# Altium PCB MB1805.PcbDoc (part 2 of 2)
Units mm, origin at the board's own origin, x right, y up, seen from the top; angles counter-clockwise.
Board outline 43 x 47.02 mm, 4 copper layers (Top Layer, Internal 1, Internal 2, Bottom Layer), stack 1.565 mm thick; 110 components, 91 nets, 377 pads, 610 vias.
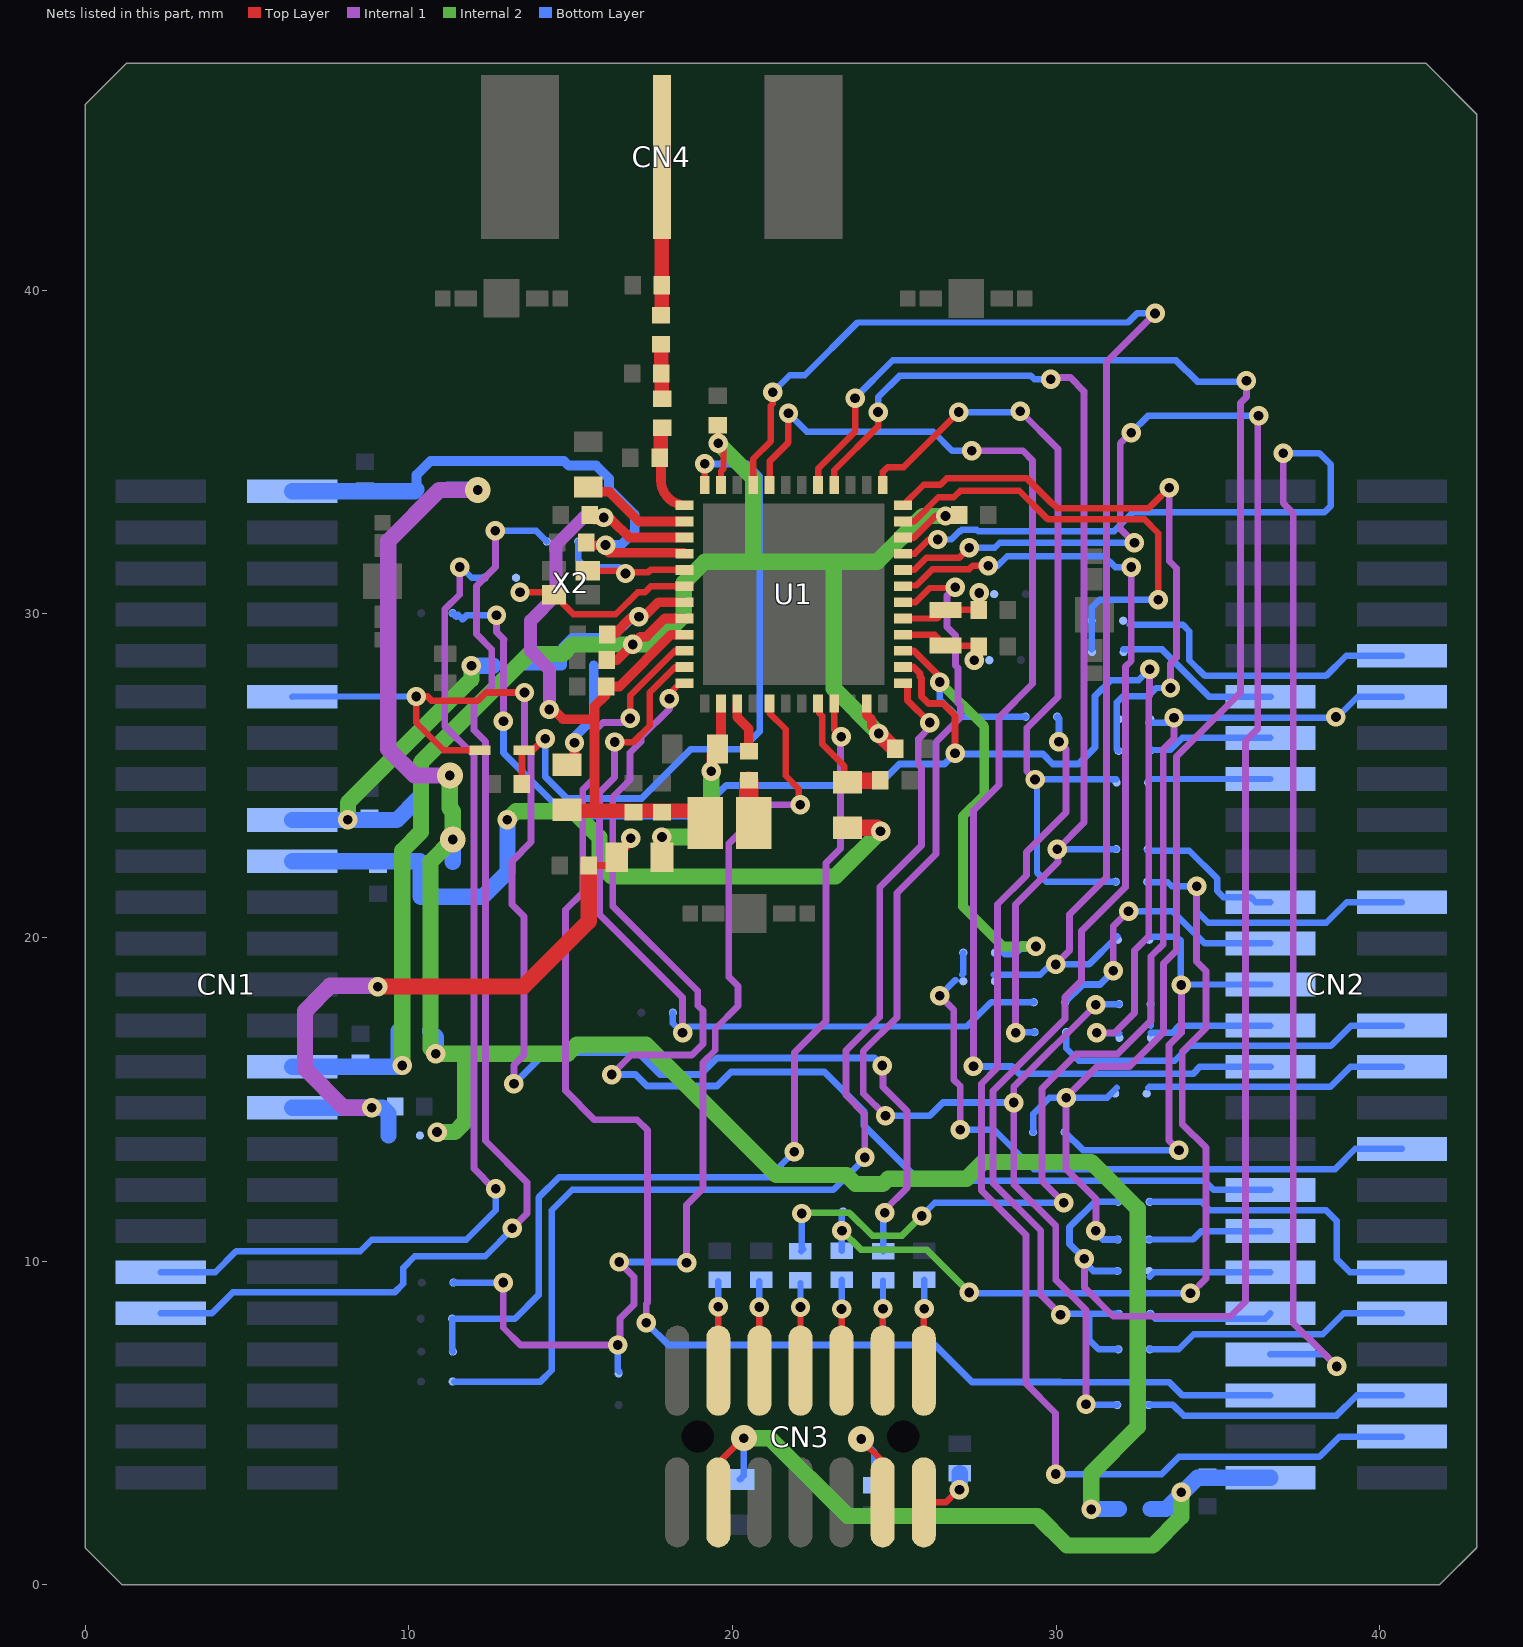
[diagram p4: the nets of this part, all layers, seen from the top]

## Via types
v1: diameter 0.6, hole 0.3, Top Layer to Bottom Layer, tented both sides, 605 vias
v2: diameter 0.8, hole 0.3, Top Layer to Bottom Layer, tented both sides, 5 vias

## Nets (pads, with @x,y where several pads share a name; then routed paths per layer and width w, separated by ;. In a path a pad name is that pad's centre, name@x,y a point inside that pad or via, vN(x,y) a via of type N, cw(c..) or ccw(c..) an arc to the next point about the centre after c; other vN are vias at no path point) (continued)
GPIO30: CN2.10 SB13.2 | length 9.8
  Bottom Layer w0.2: 32.276,29.662 33.918,29.662 34.118,29.463 34.118,28.569 34.604,28.083 38.338,28.083 38.963,28.708 CN2.10@40.688,28.708
GPIO31: CN2.11 SB10.2 | length 5.2
  Bottom Layer w0.21: SB10.2@32.077,28.905 33.271,28.905 34.737,27.438 CN2.11@36.624,27.438
GPIO32: CN2.12 R4.2 SB11.2 | length 35.9
  Internal 1 w0.21: v1(30.239,11.802) 29.562,12.479 29.562,15.337 30.624,16.399 31.901,16.399 32.931,17.429 32.931,19.422 33.312,19.803 33.312,25.822 33.643,26.153 v1(33.643,26.788)
  Internal 2 w0.21: v1(22.136,11.471) 22.195,11.471 22.216,11.493 23.611,11.493 24.318,10.786 25.235,10.786 v1(25.845,11.395)
  Bottom Layer w0.2: R4.2@22.118,10.302 22.187,10.372 22.136,10.423 v1(22.136,11.471) ; v1(25.845,11.395) 26.251,11.802 v1(30.239,11.802) ; SB11.2@32.853,26.641 33.496,26.641 v1(33.643,26.788) 38.672,26.788 39.323,27.438 CN2.12@40.688,27.438
  other v1: 38.646,26.813
GPIO33: CN2.13 SB7.2 | length 3.9
  Bottom Layer w0.2: SB7.2@32.903,25.843 SB7.2@32.935,25.812 ; SB7.2@32.938,25.794 33.523,25.794 33.897,26.168 CN2.13@36.624,26.168
GPIO34: CN2.15 SB33.1 | length 3.8
  Bottom Layer w0.2: SB33.1@32.844,24.832 32.91,24.898 CN2.15@36.624,24.898
GPIO37: CN2.21 SB26.1 | length 4.7
  Bottom Layer w0.2: SB26.1@32.824,22.679 34.119,22.679 34.977,21.821 34.977,21.44 35.167,21.25 36.005,21.25 36.167,21.088 CN2.21@36.624,21.088
GPIO38: CN2.22 R5.2 SB8.1 SB35.1 | length 35.3
  Internal 1 w0.21: v1(34.151,9.008) 34.176,9.008 34.633,9.465 34.633,13.505 33.897,14.242 33.897,16.47 34.633,17.207 34.633,18.964 34.343,19.255 v1(34.343,21.581)
  Internal 2 w0.21: v1(23.381,10.938) 23.965,10.354 25.997,10.354 v1(27.318,9.033)
  Bottom Layer w0.2: R5.2@23.376,10.328 23.376,11.402 ; v1(27.318,9.033) v1@27.343,9.008 ; SB35.1@32.829,21.708 33.448,21.708 33.575,21.581 v1(34.343,21.581) 34.343,20.813 34.701,20.454 38.351,20.454 38.985,21.088 CN2.22@40.688,21.088
  Bottom Layer w0.21: v1@27.343,9.008 v1(34.151,9.008)
GPIO39: CN2.23 SB28.1 | length 8.7
  Internal 1 w0.21: v1(31.763,18.972) 31.763,20.336 v1(32.239,20.813)
  Bottom Layer w0.2: v1(32.239,20.813) 33.597,20.813 34.592,19.818 CN2.23@36.624,19.818
  Bottom Layer w0.21: SB28.1@30.282,18 30.831,18.548 31.355,18.548 31.763,18.956 v1(31.763,18.972)
GPIO41: CN2.25 SB22.1 SB31.2 | length 14.3
  Internal 1 w0.21: v1(33.795,13.427) 33.49,13.732 33.49,16.678 33.871,17.059 v1(33.871,18.533)
  Bottom Layer w0.2: SB31.2@32.899,20.027 33.732,20.027 33.859,19.901 v1@33.859,18.533 ; v1@33.871,18.548 CN2.25@36.624,18.548
  Bottom Layer w0.21: SB22.1@30.266,13.988 30.827,13.427 v1(33.795,13.427)
GPIO42: CN2.27 SB23.2 SB36.2 | length 4.5
  Bottom Layer w0.2: 32.921,17.278 SB36.2@32.921,17.941 ; 32.93,17.044 32.921,17.053 33.585,17.053 33.811,17.278 CN2.27@36.624,17.278
GPIO43: CN2.28 SB27.1 | length 11.5
  Bottom Layer w0.2: SB27.1@30.31,17.075 30.31,16.582 30.696,16.196 33.668,16.196 34.125,16.653 38.494,16.653 39.119,17.278 CN2.28@40.688,17.278
GPIO44: CN2.29 U1.32 | length 39.4
  Top Layer w0.2: U1.32@21.145,33.983 21.145,34.711 21.73,35.297 v1(21.73,36.198)
  Internal 1 w0.21: v1(27.394,35.043) 28.207,35.043 28.969,35.043 29.274,34.738 29.274,27.842 28.237,26.805 28.237,24.709 27.445,23.917 v1(27.445,16.018)
  Bottom Layer w0.2: v1(21.73,36.198) 22.302,35.627 26.2,35.627 26.784,35.043 v1(27.394,35.043)
  Bottom Layer w0.21: v1(27.445,16.018) 28.639,16.018 28.867,15.789 34.227,15.789 34.446,16.008 CN2.29@36.624,16.008
GPIO45: CN2.30 SB24.1 | length 8.1
  Bottom Layer w0.2: 32.851,15.354 32.88,15.383 33.708,15.383 33.713,15.388 34.252,15.388 34.257,15.383 38.469,15.383 39.094,16.008 CN2.30@40.688,16.008
GPIO46: CN2.34 SB20.2 SB32.2 | length 20.3
  Internal 1 w0.21: v1(26.404,18.202) 26.835,17.771 26.835,15.612 27.039,15.408 v1(27.039,14.062)
  Bottom Layer w0.2: v1(26.404,18.202) 26.886,18.685 26.894,18.685 ; v1@27.039,14.163 v1(27.039,14.062) 28.086,14.062 29.305,12.843 38.621,12.843 39.246,13.468 CN2.34@40.688,13.468 ; 27.094,18.845 27.13,18.88 SB20.2@27.13,19.531
GPIO47: CN2.35 U1.48 | length 39.2
  Top Layer w0.2: v1(18.052,27.377) 17.906,27.377 17.898,27.385 18.371,27.858 U1.48@18.52,27.858
  Internal 1 w0.21: v1(16.269,15.764) 16.872,16.367 18.744,16.367 19.085,16.708 19.085,17.742 18.926,17.9 18.926,18.345 16.299,20.972 16.299,22.556 16.299,24.334 16.835,24.87 16.835,25.709 17.177,26.051 17.177,26.193 18.052,27.068 v1(18.052,27.377)
  Bottom Layer w0.2: 27.586,12.487 34.582,12.487 34.871,12.198 CN2.35@36.624,12.198
  Bottom Layer w0.21: v1(16.269,15.764) 16.999,15.764 17.355,15.408 19.519,15.408 19.953,15.842 22.845,15.842 24.061,14.626 24.061,14.184 25.758,12.487 27.586,12.487
GPIO49: CN2.37 SB29.1 | length 3.9
  Bottom Layer w0.2: SB29.1@32.877,10.668 34.23,10.668 34.49,10.928 CN2.37@36.624,10.928
GPIO50: CN2.39 SB12.2 | length 3.8
  Bottom Layer w0.2: 32.897,9.521 33.034,9.658 CN2.39@36.624,9.658
GPIO51: CN2.40 SB15.2 | length 9.4
  Bottom Layer w0.2: SB15.2@32.889,11.832 34.481,11.832 34.741,11.573 38.342,11.573 38.672,11.243 38.672,10.066 39.08,9.658 CN2.40@40.688,9.658
GPIO52: CN2.41 SB16.2 | length 3.8
  Bottom Layer w0.2: SB16.2@32.91,8.371 33.061,8.22 36.456,8.22 CN2.41@36.624,8.388
GPIO53: CN2.42 SB18.2 | length 8.3
  Bottom Layer w0.2: SB18.2@32.898,7.274 33.789,7.274 34.252,7.738 38.24,7.738 38.891,8.388 CN2.42@40.688,8.388
GPIO54: CN2.43 U1.21 | length 47.9
  Top Layer w0.2: U1.21@25.27,31.858 25.625,31.858 26.067,32.299 v1(26.342,32.299)
  Internal 1 w0.21: v1(37.021,34.966) 37.021,33.417 37.326,33.112 37.326,8.093 38.195,7.224 v1(38.672,6.747)
  Bottom Layer w0.2: v1(26.342,32.299) 26.759,32.299 27.013,32.553 27.048,32.553 27.09,32.595 27.546,32.595 27.588,32.553 31.79,32.553 32.375,33.138 38.291,33.138 38.494,33.341 38.494,34.611 38.138,34.966 v1(37.021,34.966) ; CN2.43@36.624,7.118 38.3,7.118 v1(38.672,6.747)
GPIO55: CN2.45 U1.46 | length 44.9
  Top Layer w0.2: v1(16.835,26.769) 16.835,26.934 16.835,27.471 18.222,28.858 U1.46@18.52,28.858
  Internal 1 w0.21: v1(16.835,26.769) 16.706,26.64 15.995,26.64 15.736,26.38 15.736,24.933 15.374,24.571 15.374,21.397 14.836,20.858 14.836,15.267 15.736,14.367 17.056,14.367 17.374,14.05 17.374,8.718 17.336,8.68 v1(17.336,8.093)
  Bottom Layer w0.2: 30.137,6.264 33.49,6.264 33.906,5.848 CN2.45@36.624,5.848
  Bottom Layer w0.21: v1(17.336,8.093) 18.016,7.413 26.253,7.413 27.402,6.264 30.137,6.264
GPIO56: CN2.46 SB34.2 | length 8.2
  Bottom Layer w0.2: SB34.2@32.865,5.556 33.611,5.556 33.941,5.226 38.667,5.226 39.289,5.848 CN2.46@40.688,5.848
GPIO57: CN2.48 SB42.2 | length 36.7
  Internal 1 w0.21: v1(29.985,3.42) 29.985,5.299 29.071,6.214 29.071,10.811 27.694,12.188 27.694,15.482 28.191,15.979 28.191,21.029 29.085,21.922 29.085,22.636 30.31,23.861 30.31,25.828 v1(30.087,26.051)
  Bottom Layer w0.2: v1(29.985,3.42) 33.262,3.42 33.795,3.953 38.138,3.953 38.764,4.578 CN2.48@40.688,4.578
  Bottom Layer w0.21: SB42.2@30.033,26.823 30.087,26.769 v1(30.087,26.051)
NetC6_1: C6.1 L4.1 U1.2 | length 5.3
  Top Layer w0.3: v1(19.347,25.142) 19.347,25.638 C6.1@19.537,25.829 ; C6.1@19.645,26.051 U1.2@19.645,27.233
  Internal 2 w0.512: v1(17.82,23.107) 19.032,23.107 19.347,23.421 v1(19.347,25.142)
NetC7_2: C7.2 D1.1 U1.36 | length 21.5
  Top Layer w0.21: C7.2@13.492,24.745 13.492,25.722 D1.1@13.554,25.784 13.827,25.784 v1@14.212,26.169 ; v1(14.212,26.145) v1@14.212,26.169 ; v1@14.297,26.254 v1@14.212,26.169 ; v1@14.332,26.289 v1@14.212,26.169 ; U1.36@19.145,33.983 v1(19.145,34.636)
  Bottom Layer w0.21: v1(14.212,26.145) 14.212,24.969 14.886,24.295 17.193,24.295 18.717,25.82 20.293,25.82 20.841,26.368 20.841,27.651 20.841,34.255 20.46,34.636 v1(19.145,34.636)
NetC8_2: C8.2 SB38.1 U1.16 X1.2 | length 2.3
  Top Layer w0.2: U1.16@25.27,29.358 26.246,29.358 X1.2@26.581,29.022 27.406,29.022 C8.2@27.445,29.062
  other v1: 27.47,28.566
NetC9_2: C9.2 SB37.1 U1.17 X1.1 | length 2.3
  Top Layer w0.2: U1.17@25.27,29.858 26.317,29.858 X1.1@26.581,30.122 27.449,30.122 C9.2@27.453,30.119
  other v1: 27.623,30.648
NetC11_2: C11.2 U1.38 | length 3.4
  Top Layer w0.3: C11.2@15.545,33.92 15.693,33.772 16.198,33.772 17.112,32.858 U1.38@18.52,32.858
NetC12_2: C12.2 L1.1 U1.37 | length 2.8
  Top Layer w0.2: L1.1@17.785,35.7 L1.1@17.831,35.745
  Top Layer w0.3: L1.1@17.785,35.7 L1.1@17.789,35.696 ; C12.2@17.789,34.865 C12.2@17.747,34.823 17.789,34.782 17.789,34.131 ccw(c18.563,34.131) U1.37@18.52,33.358
  Top Layer w0.45: C12.2@17.789,34.865 L1.1@17.789,35.696
NetC13_2: C13.2 L1.2 L2.1 | length 1.7
  Top Layer w0.45: L2.1@17.796,38.326 17.801,38.321 17.801,37.47 C13.2@17.804,37.467 ; C13.2@17.805,37.432 17.818,37.419 17.818,36.658 L1.2@17.831,36.645
NetC14_2: C14.2 CN4.1 L2.2 | length 4.9
  Top Layer w0.45: L2.2@17.796,39.226 L2.2@17.808,39.237 ; L2.2@17.811,39.231 C14.2@17.811,40.152 ; C14.2@17.816,40.157 CN4.1@17.816,44.118
  Top Layer w0.5: L2.2@17.808,39.231 L2.2@17.811,39.231 ; C14.2@17.811,40.152 C14.2@17.816,40.157 ; CN4.1@17.816,44.118 CN4.1@17.819,44.12
NetC15_1: C15.1 SB6.2 SB41.1 U1.43 | length 7.3
  Top Layer w0.3: C15.1@16.123,29.369 16.35,29.369 16.839,29.858 17.205,29.858 17.705,30.358 U1.43@18.52,30.358
  Bottom Layer w0.2: SB41.1@14.725,28.401 SB41.1@14.736,28.411
  Bottom Layer w0.3: SB6.2@13.571,28.401 SB41.1@14.725,28.401 ; SB41.1@14.736,28.411 14.736,28.942 15.048,29.254 16.247,29.254 16.905,29.912 v1(17.108,29.912)
NetC20_2: C20.2 L3.2 U1.8 | length 4.1
  Top Layer w0.2: U1.8@22.645,27.233 22.683,27.195 22.683,26.936 22.77,26.848 22.77,25.979 23.45,25.299 L3.2@23.45,24.977 ; L3.2@23.335,24.977 L3.2@23.45,24.977 ; L3.2@23.45,24.694 L3.2@23.45,24.977 ; L3.2@23.668,25.013 23.632,24.977 L3.2@23.45,24.977
  Top Layer w0.5: L3.2@23.549,24.794 23.6,24.845 C20.2@24.435,24.845
NetC23_2: C23.2 C24.1 C25.1 C26.1 L6.2 L7.2 U1.39 U1.45 | length 23.9
  Top Layer w0.3: v1(14.34,27.046) 14.466,27.046 14.616,26.896 14.765,26.747 15.735,26.747 ; C26.1@15.588,33.057 15.735,32.909 v1@16.268,32.909 ; 15.735,23.911 15.735,26.747 ; v1@16.024,32.909 v1@16.268,32.909 ; U1.45@18.52,29.358 18.107,29.358 16.508,27.759 C24.1@16.102,27.759 16.102,27.514 15.735,27.148 15.735,26.747 ; U1.39@18.52,32.358 16.818,32.358 v1@16.268,32.909
  Top Layer w0.45: L7.2@14.886,23.943 14.918,23.911 15.735,23.911 16.941,23.911 17.291,23.911 17.825,23.911 18.114,23.911 18.732,23.911 L6.2@19.098,23.545
  Internal 1 w0.4: v1(14.34,27.046) 14.34,28.283 13.765,28.859 13.765,29.791 14.546,30.572 14.546,32.126 15.399,32.98 v1(16.024,32.98)
NetCN3_4: CN3.4 R2.1 | length 2.8
  Top Layer w0.2: CN3.4@19.561,6.614 v1(19.561,8.589) v1@19.561,8.639
  Bottom Layer w0.2: v1(19.561,8.589) R2.1@19.561,9.384
NetCN3_6: CN3.6 R3.1 | length 2.8
  Top Layer w0.2: CN3.6@20.831,6.614 v1(20.831,8.579)
  Bottom Layer w0.2: v1(20.831,8.579) R3.1@20.831,9.372
NetCN3_8: CN3.8 R4.1 | length 2.7
  Top Layer w0.2: CN3.8@22.101,6.614 v1(22.101,8.579)
  Bottom Layer w0.2: v1(22.101,8.579) R4.1@22.101,9.31
NetCN3_10: CN3.10 R5.1 | length 2.8
  Top Layer w0.2: CN3.10@23.371,6.614 v1(23.371,8.519)
  Bottom Layer w0.2: v1(23.371,8.519) R5.1@23.371,9.423
NetCN3_11: CN3.11 R6.2 | length 3.9
  Top Layer w0.2: v2(23.976,4.504) 23.951,4.504 24.641,3.814 CN3.11@24.641,2.544
  Bottom Layer w0.2: v2(23.976,4.504) 24.386,4.094 R6.2@24.386,3.081
NetCN3_12: CN3.12 R7.1 | length 2.8
  Top Layer w0.2: CN3.12@24.641,6.614 24.641,8.519 v1(24.651,8.529)
  Bottom Layer w0.2: v1(24.651,8.529) R7.1@24.651,9.396
NetCN3_13: CN3.13 R9.2 | length 1.6
  Top Layer w0.2: CN3.13@25.911,2.544 26.591,2.544 v1@26.901,2.854
  Bottom Layer w0.5: v1@27.024,2.947 R9.2@27.024,3.45
  other v1: 27.013,2.937
NetCN3_14: CN3.14 R8.1 | length 2.8
  Top Layer w0.2: CN3.14@25.911,6.614 25.911,8.539 25.921,8.529 v1(25.926,8.529)
  Bottom Layer w0.2: v1(25.926,8.529) R8.1@25.926,9.424
NetL5_1: L5.1 U1.3 | length 1.6
  Top Layer w0.3: U1.3@20.145,27.233 20.145,26.809 20.505,26.448 L5.1@20.505,25.788
NetL5_2: L5.2 L6.1 | length 1.3
  Top Layer w0.6: L5.2@20.505,24.838 20.505,23.638 L6.1@20.598,23.545
NetL7_1: L7.1 SB41.2 | length 3.3
  Top Layer w0.3: L7.1@15.006,25.483 15.058,25.483 15.118,25.543 v1(15.118,26.02)
  Bottom Layer w0.3: v1(15.118,26.02) 15.118,26.191 15.711,26.784 SB41.2@15.711,28.411
NetSB1_1: SB1.1 SB2.1 SB3.1 SB4.1 SB5.1 SB43.1 | length 62.5
  Internal 1 w0.5: v2(11.265,25.01) 10.173,25.01 9.36,25.822 9.36,32.249 10.941,33.829 v2(12.129,33.829)
  Internal 2 w0.5: v1(10.871,13.988) 11.42,13.988 11.732,14.3 11.732,16.388 11.71,16.41 ; v2(11.265,25.01) 11.265,23.994 11.355,23.904 v2(11.355,23.028) 10.671,22.344 10.671,16.573 v1(10.833,16.41) 11.71,16.41 ; v1(31.087,2.327) 31.087,3.439 32.525,4.877 32.525,11.624 31.086,13.063 27.744,13.063 27.229,12.548 24.813,12.548 24.645,12.38 23.804,12.38 23.519,12.665 21.351,12.665 17.327,16.688 15.187,16.688 14.909,16.41 11.71,16.41
  Bottom Layer w0.5: SB4.1@10.651,17.107 10.84,16.918 10.84,16.41 v1(10.833,16.41) ; SB2.1@11.214,33.846 12.101,33.846 12.123,33.823 v2(12.129,33.829) ; v2(11.265,25.01) 11.269,25.006 SB3.1@11.269,24.295 ; SB1.1@11.355,22.342 v2(11.355,23.028) ; v1(31.087,2.327) 31.103,2.343 SB5.1@31.947,2.343
NetSB7_1: SB7.1 SB11.1 U1.24 | length 18.9
  Top Layer w0.2: U1.24@25.27,33.358 25.906,33.994 26.425,33.994 26.617,34.187 29.098,34.187 29.859,33.426 29.876,33.426 30.032,33.27 32.866,33.27 33.022,33.426 v1(33.496,33.9)
  Internal 1 w0.21: v1(33.496,33.9) 33.496,31.633 33.719,31.41 33.719,28.646 33.535,28.462 v1(33.535,27.71)
  Bottom Layer w0.2: SB7.1@31.928,25.767 31.878,25.817 31.878,27.264 32.077,27.462 32.842,27.462 33.089,27.71 v1(33.535,27.71)
NetSB8_2: SB8.2 SB9.2 U1.13 | length 35
  Top Layer w0.21: U1.13@25.27,27.858 25.359,27.858 25.412,27.805 25.412,27.327 v1(26.096,26.643)
  Internal 1 w0.21: v1(24.085,13.205) 24.085,14.552 23.508,15.129 23.508,16.504 24.549,17.546 24.549,21.544 25.845,22.84 25.845,25.238 25.743,25.34 25.743,26.138 26.096,26.491 v1(26.096,26.643)
  Bottom Layer w0.2: SB9.2@11.4,6.277 11.897,6.277 12.462,6.277 14.067,6.277 14.415,6.625 14.415,11.573 15.05,12.208 23.12,12.208 SB8.2@23.421,12.509 24.118,13.205 v1(24.085,13.205)
NetSB10_1: SB10.1 SB13.1 U1.23 | length 14.3
  Top Layer w0.2: U1.23@25.27,32.858 25.613,32.858 26.359,33.604 26.841,33.604 27.043,33.805 28.865,33.805 29.751,32.92 32.736,32.92 33.16,32.496 v1(33.16,30.437)
  Bottom Layer w0.2: SB10.1@31.102,28.905 31.102,29.7 31.105,29.704 31.105,30.2 31.343,30.437 v1(33.16,30.437)
NetSB12_1: SB12.1 SB15.1 U1.20 | length 53.8
  Top Layer w0.2: U1.20@25.27,31.358 25.621,31.358 26.003,31.741 27.013,31.741 v1(27.318,32.045)
  Internal 1 w0.21: v1(30.874,10.074) 30.874,9.185 31.763,8.296 35.395,8.296 35.852,8.754 35.852,26.076 36.233,26.457 36.233,36.075 36.279,36.121 36.267,36.133 v1(36.256,36.121) ; v1(32.322,35.601) 31.98,35.26 31.98,32.637 v1(32.42,32.198)
  Bottom Layer w0.2: v1(27.318,32.045) 28.105,32.045 28.258,32.198 32.351,32.198 32.434,32.116 32.468,32.15 v1(32.42,32.198)
  Bottom Layer w0.21: SB12.1@31.897,9.698 31.149,9.698 30.874,9.973 v1(30.874,10.074) 30.417,10.532 30.417,11.055 31.194,11.832 SB15.1@31.914,11.832 ; v1(32.322,35.601) 32.842,36.121 v1(36.256,36.121)
NetSB14_2: SB14.2 SB17.2 U1.9 | length 30
  Top Layer w0.2: U1.9@23.145,27.233 23.145,26.418 v1(23.362,26.201)
  Internal 1 w0.21: v1(21.912,13.376) 21.912,16.446 22.888,17.422 22.888,22.299 23.335,22.747 23.335,26.174 v1(23.362,26.201)
  Bottom Layer w0.2: SB14.2@11.359,7.205 11.339,7.224 SB17.2@11.339,8.221 13.278,8.221 14.008,8.952 14.008,11.964 14.643,12.598 21.134,12.598 v1(21.912,13.376)
NetSB16_1: SB16.1 SB18.1 U1.19 | length 36.7
  Top Layer w0.2: U1.19@25.27,30.858 25.29,30.878 25.678,30.878 26.185,31.385 27.318,31.385 27.42,31.487 v1(27.902,31.487)
  Internal 1 w0.21: v1(30.137,8.347) 29.528,8.957 29.528,10.938 28.054,12.412 28.054,15.256 30.277,17.48 30.277,18.156 30.788,18.666 30.788,20.199 32.144,21.555 32.144,28.372 32.322,28.55 v1(32.322,31.447)
  Internal 2 w0.21: v1@30.087,8.398 v1(30.137,8.347)
  Bottom Layer w0.2: v1(27.902,31.487) 28.191,31.487 28.487,31.783 28.943,31.783 31.489,31.783 31.825,31.447 v1(32.322,31.447) ; v1@30.417,8.371 31.026,8.371 ; SB18.1@31.923,7.274 31.312,7.274 31.026,7.56 31.026,8.371 ; SB16.1@31.935,8.371 31.026,8.371
NetSB19_2: SB19.2 SB21.2 U1.5 | length 32.6
  Top Layer w0.2: U1.5@21.145,27.233 21.145,26.932 21.645,26.432 21.645,24.996 22.043,24.597 v1@22.043,24.136
  Internal 1 w0.21: v1(12.916,9.338) 12.916,7.941 13.45,7.407 v1(16.452,7.407) 16.523,7.407 16.523,8.225 16.959,8.661 16.959,9.511 v1(16.498,9.973) ; v1(18.58,9.947) 18.58,11.736 19.085,12.24 19.085,16.133 19.468,16.516 19.468,17.181 20.168,17.881 20.168,18.502 19.886,18.784 19.886,22.907 21.083,24.104 v1(22.096,24.104)
  Bottom Layer w0.2: SB19.2@11.375,9.337 11.402,9.363 11.427,9.338 v1(12.916,9.338) ; v1(16.452,7.407) 16.452,6.632 SB21.2@16.506,6.578
  Bottom Layer w0.21: v1(16.498,9.973) 18.555,9.973 v1(18.58,9.947)
NetSB20_1: SB20.1 SB42.1 U1.15 | length 16.7
  Top Layer w0.21: U1.15@25.27,28.858 25.607,28.858 26.429,28.036 26.374,27.98 26.402,27.952 v1(26.402,27.893)
  Internal 2 w0.3: v1(26.402,27.893) 27.781,26.513 27.781,24.409 27.121,23.749 27.121,20.96 28.358,19.724 v1(29.377,19.724)
  Bottom Layer w0.21: v1@26.402,27.914 v1(26.402,27.893) 26.402,27.356 26.935,26.823 SB42.1@29.058,26.823
  Bottom Layer w0.3: 28.433,19.531 28.717,19.531 28.91,19.724 v1(29.377,19.724)
NetSB22_2: SB22.2 SB24.2 SB29.2 U1.29 | length 50
  Top Layer w0.2: U1.29@22.645,33.983 22.645,34.484 23.787,35.627 v1(23.787,36.668)
  Internal 1 w0.21: v1(31.23,10.938) 31.23,11.92 30.31,12.84 v1(30.31,15.053) 31.27,16.014 32.267,16.014 33.316,17.063 33.316,19.197 33.719,19.599 33.719,25.594 35.7,27.575 35.7,36.516 35.882,36.698 v1(35.882,37.202)
  Bottom Layer w0.2: v1(23.787,36.668) 24.955,37.836 ; SB22.2@29.291,13.988 29.291,14.549 29.794,15.053 v1(30.31,15.053) 31.574,15.053 31.876,15.354
  Bottom Layer w0.21: 24.955,37.836 33.705,37.836 34.365,37.176 35.908,37.176 v1(35.882,37.202) ; v1(31.23,10.938) 31.2,10.938 31.19,10.928 31.451,10.668 SB29.2@31.902,10.668
NetSB23_1: SB23.1 SB25.1 U1.14 | length 46.5
  Top Layer w0.21: U1.14@25.27,28.358 25.597,28.358 25.794,28.161 25.794,28.062 25.843,28.013 25.843,27.449 26.06,27.233 26.501,27.233 26.879,26.855 v1(26.879,25.691)
  Internal 1 w0.21: v1(12.708,29.961) 12.708,29.44 12.942,29.206 12.922,29.186 v1(12.922,26.683) ; v1(31.255,17.059) 31.814,17.059 32.423,17.669 32.423,19.599 32.861,20.037 32.861,27.44 32.889,27.468 v1(32.889,28.286)
  Bottom Layer w0.2: v1(31.255,17.059) 31.275,17.059 31.29,17.044 31.955,17.044
  Bottom Layer w0.21: SB25.1@11.352,30.022 11.462,29.912 11.522,29.971 11.635,29.858 11.661,29.832 11.79,29.961 v1(12.708,29.961) ; v1(12.922,26.683) 12.922,25.708 12.942,25.688 14.883,23.747 18.858,23.747 19.805,24.693 24.491,24.693 25.164,25.365 26.553,25.365 v1(26.879,25.691) 26.899,25.671 29.592,25.671 29.897,25.365 30.693,25.365 31.206,25.878 31.206,27.464 31.692,27.95 32.553,27.95 v1(32.889,28.286)
NetSB26_2: SB26.2 SB27.2 U1.28 | length 33.1
  Top Layer w0.2: U1.28@23.145,33.983 23.145,34.438 24.499,35.792 v1(24.499,36.236)
  Internal 1 w0.21: v1(28.749,17.053) 28.749,21.018 30.061,22.33 v1@30.061,22.495 ; v1(29.833,37.252) 29.833,37.151 29.985,37.303 30.442,37.303 30.866,36.879 30.866,23.554 v1(30.036,22.724)
  Bottom Layer w0.2: v1(24.499,36.236) 24.499,36.694 25.159,37.354 29.223,37.354 29.325,37.252 v1(29.833,37.252) ; v1(28.749,17.053) 28.772,17.075 SB27.2@29.335,17.075 ; v1@30.087,22.731 SB26.2@31.858,22.731
NetSB28_2: SB28.2 SB30.2 U1.47 | length 26
  Top Layer w0.2: v1(16.358,26.041) 16.942,26.041 17.44,26.54 17.44,27.571 18.227,28.358 U1.47@18.52,28.358
  Internal 1 w0.21: v1(16.358,26.041) 16.358,24.95 15.888,24.481 15.888,20.717 18.458,18.147 v1(18.458,17.053)
  Bottom Layer w0.2: SB30.2@18.157,17.676 18.157,17.353 v1(18.458,17.053) 18.655,17.25 27.242,17.25 27.992,18 SB28.2@29.307,18
NetSB31_1: SB31.1 SB32.1 U1.33 | length 41.7
  Top Layer w0.2: U1.33@20.645,33.983 20.645,34.796 21.18,35.331 21.18,36.426 21.247,36.494 v1(21.247,36.846)
  Internal 1 w0.21: v1@29.985,19.219 v1(29.985,19.168) 30.417,19.599 30.417,20.717 31.56,21.86 31.56,37.786 v1(33.058,39.284)
  Bottom Layer w0.2: v1(21.247,36.846) 21.772,37.371 22.229,37.371 23.864,39.005 32.22,39.005 32.5,39.284 v1(33.058,39.284) ; 28.069,18.845 29.511,18.845 29.833,19.168 v1(29.985,19.168) 31.017,19.168 31.844,19.995 SB31.1@31.89,20.041
NetSB33_2: SB33.2 SB35.2 U1.25 | length 25.8
  Top Layer w0.2: U1.25@24.645,33.983 24.645,34.386 24.793,34.535 25.286,34.535 v1(26.988,36.236)
  Internal 1 w0.21: v1(28.893,36.262) 30.061,35.093 30.061,27.436 29.096,26.471 29.096,25.137 v1(29.35,24.883)
  Bottom Layer w0.2: v1(26.988,36.236) v1@28.918,36.236 ; SB35.2@31.842,21.723 29.699,21.723 29.41,22.012 29.41,24.833 29.35,24.893 SB33.2@31.852,24.893
NetSB34_1: SB34.1 SB36.1 U1.18 | length 40.2
  Top Layer w0.2: U1.18@25.27,30.358 25.656,30.358 26.099,30.801 26.708,30.801 26.861,30.953 26.886,30.928 v1(26.886,30.826)
  Internal 1 w0.21: v1(24.727,14.494) 24.041,15.18 24.041,16.486 25.083,17.528 25.083,21.374 26.287,22.579 26.287,26.035 27.05,26.797 27.05,27.159 26.967,27.242 26.967,28.333 26.894,28.405 26.894,29.332 26.632,29.594 26.632,30.572 v1(26.886,30.826) ; v1(30.925,5.579) 30.925,8.486 29.992,9.419 29.992,11.084 28.69,12.386 v1(28.69,14.9) 28.69,15.383 v1(31.23,17.923)
  Bottom Layer w0.2: v1@30.95,5.556 SB34.1@31.89,5.556 ; v1(31.23,17.923) 31.248,17.941 SB36.1@31.946,17.941
  Bottom Layer w0.21: v1(24.727,14.494) 26.099,14.494 26.505,14.9 v1(28.69,14.9)
NetSB39_1: SB39.1 U1.42 X2.1 | length 5.9
  Top Layer w0.2: v1(13.434,30.673) 14.091,30.673 ; X2.1@14.141,30.678 14.356,30.463 14.433,30.541 X2.1@14.433,30.463 ; X2.1@14.481,30.589 15.084,29.986 16.394,29.986 17.072,30.664 17.285,30.664 17.48,30.858 U1.42@18.52,30.858
  Bottom Layer w0.2: v1(13.434,30.673) 13.454,30.693 v1@13.476,30.67
NetSB40_1: SB40.1 U1.41 X2.3 | length 5.3
  Top Layer w0.2: X2.3@15.531,31.339 16.604,31.339 v1(16.695,31.248) 16.739,31.292 17.403,31.292 17.469,31.358 U1.41@18.52,31.358
  Bottom Layer w0.2: SB40.1@15.235,32.238 15.235,31.674 15.462,31.447 16.496,31.447 v1(16.695,31.248)
NRST: CN1.12 D1.2 R7.2 | length 41.9
  Top Layer w0.2: v1(10.228,27.448) 10.228,26.636 11.081,25.784 D1.2@12.204,25.784
  Top Layer w0.21: v1(10.228,27.448) 10.573,27.448 10.703,27.318 12.131,27.318 12.385,27.571 v1(13.572,27.571)
  Internal 1 w0.21: v1(13.246,15.478) 13.246,16.059 13.554,16.367 13.554,20.652 13.184,21.022 13.184,22.354 13.778,22.948 13.778,25.678 13.572,25.884 v1(13.572,27.571) ; v1(24.626,16.043) 24.626,15.769 24.651,15.743 24.651,15.383 25.392,14.642 25.392,12.263 24.702,11.573 v1(24.702,11.493)
  Bottom Layer w0.2: CN1.12@6.398,27.438 6.408,27.448 v1(10.228,27.448) ; R7.2@24.658,10.303 v1@24.658,11.479
  Bottom Layer w0.21: v1(13.246,15.478) 14.218,16.45 17.082,16.45 17.763,15.768 19.017,15.768 19.526,16.278 24.391,16.278 v1(24.626,16.043)
OSC_IN: CN1.39 SB39.2 | length 32.8
  Internal 1 w0.21: v1(11.572,31.447) 11.572,30.602 11.106,30.135 11.106,26.537 12.01,25.632 12.01,12.86 12.637,12.233 v1(12.688,12.233)
  Bottom Layer w0.2: CN1.39@2.334,9.658 4.017,9.658 4.661,10.302 8.496,10.302 8.852,10.659 11.773,10.659 12.688,11.573 v1(12.688,12.233) ; v1(11.572,31.447) 11.592,31.467 11.942,31.117 SB39.2@12.337,31.117
OSC_OUT: CN1.41 SB40.2 | length 37.1
  Internal 1 w0.21: v1(12.673,32.568) 12.673,31.453 12.087,30.867 12.087,29.38 12.561,28.905 12.561,27.759 12.01,27.208 12.01,26.406 12.015,26.406 12.37,26.051 12.37,13.719 13.653,12.437 13.653,11.471 v1(13.196,11.014)
  Bottom Layer w0.2: CN1.41@2.334,8.388 3.915,8.388 4.56,9.033 9.557,9.033 9.825,9.301 9.825,9.79 10.186,10.151 12.357,10.151 13.221,11.014 v1(13.196,11.014) ; v1(12.673,32.568) 13.93,32.568 SB40.2@14.26,32.238
VDD1: C2.2 C10.1 CN1.2 SB2.2 U1.40 | length 16.9
  Top Layer w0.3: C10.1@15.484,32.202 15.568,32.118 v1@15.989,32.118 ; v1@16.062,32.045 v1@16.078,32.062 ; v1(16.078,32.126) v1@16.078,32.062 ; U1.40@18.52,31.858 18.485,31.893 16.177,31.893 16.078,31.992 v1@16.078,32.062
  Bottom Layer w0.3: SB2.2@10.239,33.846 10.239,34.296 10.671,34.727 14.794,34.727 14.936,34.585 15.788,34.585 16.187,34.187 16.187,33.867 16.977,33.077 16.977,32.55 16.553,32.126 v1(16.078,32.126)
  Bottom Layer w0.5: CN1.2@6.398,33.788 8.649,33.788 10.181,33.788 SB2.2@10.239,33.846
VDD3: C3.2 CN1.18 SB3.2 SB6.1 | length 11.2
  Internal 2 w0.5: v1(8.116,23.638) 8.116,24.162 11.933,27.98 v1(11.933,28.398)
  Bottom Layer w0.5: CN1.18@6.398,23.628 9.627,23.628 SB3.2@10.294,24.295 ; v1(11.933,28.398) 12.594,28.398 SB6.1@12.596,28.401
VDD4: C4.2 C16.1 C17.1 C18.1 C19.1 CN1.30 SB4.2 U1.11 U1.22 U1.35 U1.44 | length 52.1
  Top Layer w0.2: v1@19.546,35.287 C18.1@19.546,35.837 ; v1(19.561,35.271) 19.722,35.111 19.722,34.482 19.645,34.405 U1.35@19.645,33.983 ; U1.22@25.27,32.358 25.608,32.358 26.277,33.026
  Top Layer w0.3: C19.1@16.108,28.575 16.434,28.575 17.156,29.297 17.342,29.297 17.903,29.858 U1.44@18.52,29.858 ; U1.11@24.145,27.233 24.145,26.875 24.304,26.716 24.304,26.525 v1(24.524,26.305)
  Top Layer w0.5: v1(24.524,26.305) 24.998,25.831 C16.1@25.024,25.831 ; v1@26.581,33.026 v1(26.583,33.026) ; v1(26.583,33.026) v1(26.583,33.026) ; v1@26.596,33.011 v1(26.583,33.026)
  Internal 2 w0.5: v1(9.795,16.046) 9.795,22.683 10.375,23.263 10.375,25.412 13.724,28.761 14.759,28.761 15.055,29.057 v1(16.92,29.057) 17.603,29.057 18.495,29.949 18.495,30.964 19.145,31.614 20.638,31.614 ; v1(19.561,35.271) 20.638,34.195 20.638,31.614 ; v1(24.524,26.305) 24.519,26.305 23.127,27.697 23.127,31.614 ; v1(26.583,33.026) 25.981,33.026 25.934,32.979 25.886,33.026 24.473,31.614 23.127,31.614 ; 20.638,31.614 23.127,31.614
  Bottom Layer w0.5: CN1.30@6.398,16.008 v1@9.795,16.008 ; SB4.2@9.676,17.107 9.676,16.165 v1(9.795,16.046)
VDD5: C21.1 C27.2 CN1.32 L4.2 SB43.2 | length 21.5
  Top Layer w0.21: C21.1@15.557,22.221 16.165,22.221 L4.2@16.422,22.478 16.858,22.914 v1(16.858,23.071)
  Top Layer w0.5: v1(9.034,18.482) 13.536,18.482 15.557,20.503 C21.1@15.557,22.221
  Internal 1 w0.5: v1(8.852,14.738) 7.993,14.738 6.792,15.94 6.792,17.73 7.57,18.508 9.007,18.508 v1(9.034,18.482)
  Bottom Layer w0.5: CN1.32@6.398,14.738 v1(8.852,14.738) 9.194,14.738 9.366,14.566 SB43.2@9.366,13.88
VDD14: C5.2 C22.2 CN2.49 CN3.3 SB5.2 | length 23.8
  Top Layer w0.2: CN3.3@19.561,2.544 19.561,3.764 20.326,4.529 v2(20.351,4.529)
  Internal 2 w0.5: v2(20.351,4.529) 21.154,4.529 23.559,2.124 29.426,2.124 30.341,1.21 32.984,1.21 33.871,2.097 v1(33.871,2.861)
  Bottom Layer w0.2: C22.2@20.231,3.254 20.351,3.375 v2(20.351,4.529)
  Bottom Layer w0.5: SB5.2@32.922,2.343 33.404,2.343 34.37,3.308 CN2.49@36.624,3.308
VDDA: C1.2 CN1.20 L3.1 SB1.2 | length 24.3
  Top Layer w0.5: L3.1@23.549,23.394 24.464,23.394 v1(24.577,23.282)
  Internal 2 w0.5: v1(13.043,23.638) 13.309,23.904 15.086,23.904 15.888,23.102 15.888,22.266 16.269,21.885 19.771,21.885 23.18,21.885 v1(24.577,23.282)
  Bottom Layer w0.5: CN1.20@6.398,22.358 10.339,22.358 SB1.2@10.368,22.329 10.368,21.259 12.28,21.259 13.043,22.022 v1(13.043,23.638)
pads on no net: CN1.3 CN1.4 CN1.5 CN1.10 CN1.11 CN1.16 CN1.19 CN1.21 CN1.23 CN1.27 CN1.43 CN1.48 CN1.50 CN2.1 CN2.3 CN2.4 CN2.5 CN2.6 CN2.16 CN2.17 CN2.18 CN2.19 CN2.24 CN2.31 CN2.33 CN2.36 CN2.47 CN3.1 CN3.2 CN3.9 CN3.NPTH1 CN3.NPTH2 Designator15.1

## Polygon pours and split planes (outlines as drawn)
GND on Top Layer "GND_L01_P018" (solid, remove dead copper, pour order 18): -3.864,47.015 44.094,47.015 44.094,-0.965 -3.886,-0.965 -3.886,47.015
GND on Top Layer "GND_L01_P014" (solid, pour order 14): 19.271,26.972 18.692,26.393 18.692,24.979 18.52,24.807 17.061,24.807 17.061,25.715 18.579,27.233 18.805,27.233 19.145,27.233
GND on Internal 1 "Internal 1-GND" (solid, remove dead copper, pour order 13): -2.431,47.015 15.908,47.015 15.908,31.976 20.124,31.976 20.124,47.015 45.042,47.015 45.042,-1.603 -2.431,-1.603
GND on Internal 2 "Internal 2-GND" (solid, remove dead copper, pour order 11): -5.171,47.015 46.823,47.015 46.823,-0.705 -5.171,-0.705 -5.171,41.154
GND on Bottom Layer "Bottom Layer-GND" (solid, remove dead copper, pour order 7): -2.082,47.015 45.441,47.015 45.441,-1.454 -2.082,-1.454

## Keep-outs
Top Layer:
  rectangle: 17.571,38.711 17.965,38.814
  rectangle: 19.06,27.675 24.731,33.447
  rectangle: 17.544,36.142 18.052,36.242
Keep-Out Layer:
  lines w0.1: 0,45.263 0,39.878 0,1.139 1.139,0 41.852,0 42.504,0.647 43.001,1.141 ; 0.003,45.265 0.003,45.682 1.321,47 41.443,47 43,45.443 43,39.982 43,1.141

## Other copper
Top Layer:
  region net NetC12_2: 18.06,33.355 18.207,33.208 18.255,33.208 18.255,33.253 18.153,33.355 18.061,33.355

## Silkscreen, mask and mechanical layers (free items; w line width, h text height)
Top Overlay:
  lines w0.05: -0.592,0 1.139,0 ; 0,-0.5 0,1.139
  lines w0.1: 9.182,20.742 31.182,20.742 31.182,39.742 9.182,39.742 9.182,20.742
  lines w0.15: 18.06,34.908 19.145,37.202 ; 18.155,23.529 18.54,22.202 18.765,22.078
  text "L" at 1.959,36.409 h7.62
  text "MB1805B" at 2.769,1.988 h2.5
Bottom Overlay:
  lines w0.2: 33.246,18.025 33.897,18.025 ; 33.246,26.389 33.897,26.389 ; 33.262,16.983 33.846,16.983
  text "H" at 11.274,36.34 h7.62
  text "C" at 18.465,35.073 h7.62
  text "I" at 23.261,34.794 h7.62
Top Solder:
  lines w1: 9.182,28.058 9.182,20.742 14.212,20.742 ; 9.182,33.925 9.182,39.742 9.944,39.742 ; 16.584,20.754 17.789,20.739 ; 19.816,39.732 24.219,39.767 ; 23.371,20.742 31.153,20.742 31.153,26.813 ; 30.137,39.792 31.153,39.792 31.153,34.241
M1-Board Shape:
  lines w0.1: 0,1.139 0,39.878 0,45.686 1.314,47 41.444,47 43,45.444 43,39.982 43.001,1.141 41.852,0 1.139,0 0,1.139
M4-Bottom Dimensions:
  lines w0.1: 2.334,-5 2.334,33.788 ; 36.624,-5 36.624,33.788
  lines w0.254: 2.334,-5.254 2.334,-4.746 ; 3.858,-5.508 2.334,-5 ; 3.858,-4.492 2.334,-5 ; 12.217,-5 2.334,-5 ; 26.742,-5 36.624,-5 ; 35.1,-5.508 36.624,-5 ; 35.1,-4.492 36.624,-5 ; 36.624,-5.254 36.624,-4.746
  text "34.29 (mm)" at 12.471,-5.914 h1.52
  text "CN1/CN2 spacing" at 12.489,-7.193 h1
Drill Drawing:
  drawing of 315 lines, arcs and shapes, not listed
  text "mils" at 31.397,176.353 h2.54
  text "mils" at 19.916,176.302 h2.54
  text "Layer" at -0.699,115.405 h1.52
  text "Name" at 9.713,115.405 h1.52
  text "Material" at 33.329,115.405 h1.52
  text "Thickness" at 55.167,115.405 h1.52
  text "Constant" at 71.673,115.405 h1.52
  text "Board Layer Stack" at 86.147,115.405 h1.52
  text "Top Overlay" at 9.713,112.357 h1.52
  text "Top Solder" at 9.713,109.309 h1.52
  text "Solder Resist" at 33.329,109.309 h1.52
  text "0,70mil" at 55.167,109.309 h1.52
  text "4.2" at 71.673,109.309 h1.52
  text "1" at -0.699,106.261 h1.52
  text "Top Layer" at 9.713,106.261 h1.52
  text "1,60mil" at 55.167,106.261 h1.52
  text "Dielectric 1" at 9.713,103.213 h1.52
  text "FR-4" at 33.329,103.213 h1.52
  text "3,00mil" at 55.167,103.213 h1.52
  text "3.7" at 71.673,103.213 h1.52
  text "2" at -0.699,100.165 h1.52
  text "Internal 1" at 9.713,100.165 h1.52
  text "1,20mil" at 55.167,100.165 h1.52
  text "Dielectric 3" at 9.713,97.117 h1.52
  text "50,00mil" at 55.167,97.117 h1.52
  text "4.5" at 71.673,97.117 h1.52
  text "3" at -0.699,94.069 h1.52
  text "Internal 2" at 9.713,94.069 h1.52
  text "1,20mil" at 55.167,94.069 h1.52
  text "Dielectric 2" at 9.713,91.021 h1.52
  text "3,00mil" at 55.167,91.021 h1.52
  text "3.7" at 71.673,91.021 h1.52
  text "4" at -0.699,87.973 h1.52
  text "Bottom Layer" at 9.713,87.973 h1.52
  text "1,60mil" at 55.167,87.973 h1.52
  text "Bottom Solder" at 9.713,84.925 h1.52
  text "Solder Resist" at 33.329,84.925 h1.52
  text "0,70mil" at 55.167,84.925 h1.52
  text "4.2" at 71.673,84.925 h1.52
  text "Bottom Overlay" at 9.713,81.877 h1.52
  text "Symbol" at -0.519,73.911 h2.16
  text "Count" at 7.943,73.911 h2.16
  text "Hole Size" at 16.728,73.911 h2.16
  text "Plated" at 32.277,73.911 h2.16
  text "Hole Type" at 39.705,73.911 h2.16
  text "Drill Layer Pair" at 50.519,73.911 h2.16
  text "Via/Pad" at 71.018,73.911 h2.16
  text "Pad Shape" at 79.88,73.911 h2.16
  text "Template" at 91.456,73.911 h2.16
  text "Description" at 105.878,73.911 h2.16
  text "610" at 7.943,70.183 h1.8
  text "11,81mil (0,30mm)" at 16.728,70.183 h1.8
  text "PTH" at 32.277,70.183 h1.8
  text "Round" at 39.705,70.183 h1.8
  text "Top Layer - Bottom Layer" at 50.519,70.183 h1.8
  text "Via" at 71.018,70.183 h1.8
  text "Rounded" at 79.88,70.183 h1.8
  text "(Mixed)" at 91.456,70.183 h1.8
  text "2" at 7.943,66.454 h1.8
  text "39,37mil (1,00mm)" at 16.728,66.454 h1.8
  text "NPTH" at 32.277,66.454 h1.8
  text "Round" at 39.705,66.454 h1.8
  text "Top Layer - Bottom Layer" at 50.519,66.454 h1.8
  text "Pad" at 71.018,66.454 h1.8
  text "Rounded" at 79.88,66.454 h1.8
  text "c0hn100m105p-1" at 91.456,66.454 h1.8
  text "612 Total" at 7.943,62.726 h1.8

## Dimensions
1.321,47 to 0,0 on M3-Top Dimensions
43,1.141 to 0,1.139 on M3-Top Dimensions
